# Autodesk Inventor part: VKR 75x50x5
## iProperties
Created: 2001-12
Part Number: VKR 75x50x5
Material: S235JRG2
Document SubType Name: Modeling
Designer: Tobben
Control State: 0
Master: False
Checked Out: False
Shininess: 64.0
Length Units: 11269
Angle Units: 11279
Time Units: 11290
Mass Units: 11283
Length Display Precision: 3
Angle Display Precision: 2
Density: 0.0
Volumn: 0.0
Area: 0.0
PropertySet Name: Model Information
Author: Tobben
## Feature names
1. Extrusion1
